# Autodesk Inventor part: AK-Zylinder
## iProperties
Created: 2004-01
Part Number: AK-Zylinder
Material: Messing (weiches, gelbes Messing)
Document SubType Name: Modellieren
Designer: Ulrich
Control State: 0
Master: False
Checked Out: False
Shininess: 20.0
Angle Display Precision: 2
Document Length Units: 11269
Document Angle Units: 11279
Document Time Units: 11290
Document Mass Units: 11283
Document Length Units Precision: 3
Document Angle Units Precision: 2
Density: 0.0
Volumn: 0.0
Area: 0.0
PropertySet Name: Model Information
Author: Ulrich
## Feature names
1. Zylinder [Extrusion]
2. Befestigungsbund [Extrusion]
3. Befestigungsbohrung [Hole]
